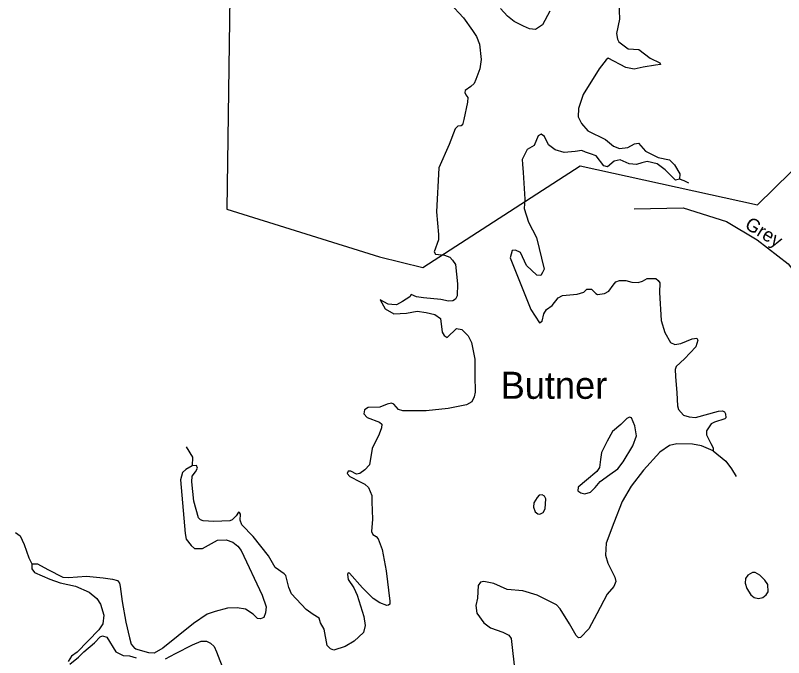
# Model space of a CAD drawing. Extents: x 2056842 to 2160602, y 826753 to 1016856.
# Drawn here: x 2065133 to 2070531, y 880850 to 885359 of the extents above; entities that cross this region are included whole.
import ezdxf

# ---------------------------------------------------------------- set-up
doc = ezdxf.new("R2010")
doc.units = 0
for name, color, linetype in [('Exist Boundary Land Use Reservation Military US Department of Defense', 7, 'Continuous'), ('Exist Hydrographic Lake Shore', 7, 'Continuous'), ('Exist Hydrographic Lake Shore Label', 7, 'Continuous'), ('Exist Hydrographic Misc Water Feature', 7, 'Continuous'), ('Exist Road Non-System Type 51', 7, 'Continuous'), ('Exist Road Non-System Type 51 Label', 7, 'Continuous')]:
    doc.layers.add(name, color=color, linetype=linetype)

msp = doc.modelspace()

# ---------------------------------------------------------------- linework, layer by layer
at = {"layer": 'Exist Boundary Land Use Reservation Military US Department of Defense'}
msp.add_lwpolyline([(2067058.3, 892019.1), (2067059.5, 891358.5), (2066982.6, 890921.4), (2067567.8, 890285), (2067430.4, 890017.5), (2067627.8, 889522.4), (2067456.3, 889295), (2067709.3, 888998.5), (2067120, 887398.5), (2066967.8, 887049.6), (2067058.5, 886712.6), (2066509.4, 886235.5), (2066262.8, 886013.6), (2066639, 885490.3), (2066618.5, 883998.2), (2067691.7, 883663.3), (2067994.8, 883588.2), (2069101.6, 884301.6), (2070346.7, 884029), (2071050.9, 884719.7)], dxfattribs=at)
at = {"layer": 'Exist Hydrographic Lake Shore'}
for points in [[(2069373.7, 885453.7), (2069376.3, 885332.1), (2069357.3, 885230.7), (2069362.3, 885192.7), (2069373.7, 885173.7), (2069438.7, 885124.1), (2069512.8, 885120.2), (2069592.7, 885058.3), (2069660.9, 885026.5), (2069664.9, 885014.4), (2069629.5, 885009.6), (2069544.3, 884994.4), (2069479.7, 884981.8), (2069421.5, 884991.9), (2069298.6, 885057.8), (2069284.7, 885047.6), (2069235.3, 884983), (2069122.6, 884804.4), (2069088.5, 884704.3), (2069087.2, 884647.3), (2069111.2, 884600.4), (2069155.6, 884548.5), (2069278.4, 884487.7), (2069334.1, 884440.8), (2069378.3, 884424.3), (2069435.3, 884430.6), (2069482.1, 884456), (2069511.2, 884461.1), (2069560.6, 884406.6), (2069649.2, 884361), (2069727.7, 884345.8), (2069763.2, 884309), (2069801.2, 884245.7), (2069799.9, 884208.9)], [(2068185.5, 885445.4), (2068280.4, 885341.5), (2068343.7, 885251.6), (2068371.6, 885211), (2068393.1, 885157.2), (2068404.5, 885049.5), (2068395.7, 884983.6), (2068367.8, 884908.9), (2068356.4, 884881), (2068332.4, 884860.7), (2068293.1, 884832.1), (2068291.8, 884818.1), (2068298.2, 884801.7), (2068310.8, 884781.4), (2068308.3, 884749.7), (2068284.2, 884628.1), (2068274.1, 884591.4), (2068265.2, 884583.8), (2068242.5, 884580), (2068222.2, 884561.2), (2068181.7, 884453.3), (2068107, 884289.1), (2068090.5, 883980.3), (2068105.1, 883819.6), (2068105.2, 883783.6), (2068075.4, 883697.6), (2068083.5, 883681.6), (2068147.6, 883675.7), (2068184.2, 883662), (2068203.2, 883640.4), (2068226, 883608.7), (2068238.7, 883473.2), (2068237.4, 883390.8), (2068226, 883365.9), (2068205.7, 883354.5), (2068176.6, 883353.2), (2068120.9, 883364.6), (2068000.6, 883374.7), (2067950, 883382.3), (2067914.5, 883398.8), (2067903.1, 883383.6), (2067852.2, 883349.7), (2067811.7, 883325.6), (2067778.8, 883328.1), (2067752.2, 883330.7), (2067695.2, 883361.1), (2067730.7, 883297.7), (2067791.5, 883263.5), (2067880.1, 883268.6), (2067954.8, 883281.2), (2068019.4, 883272.4), (2068078.9, 883258.4), (2068120.7, 883231.8), (2068130.4, 883135.8), (2068146.5, 883111.7), (2068166.6, 883097.8), (2068233.3, 883161.1), (2068268.8, 883153.5), (2068314.5, 883110), (2068338.4, 883062.3), (2068361.2, 882944.5), (2068361.1, 882830.2)], [(2068888.7, 885389.6), (2068835.5, 885292.1), (2068787.4, 885259.2), (2068745.1, 885264.2), (2068702.1, 885282), (2068638, 885316.2), (2068590.3, 885354.4), (2068540.2, 885408.3)], [(2069799.9, 884208.9), (2069770.8, 884202.6), (2069697.4, 884273.6), (2069641.6, 884316.6), (2069571.8, 884333.1), (2069533.8, 884324.2), (2069495.8, 884312.8), (2069446.4, 884316.6), (2069383.1, 884344.5), (2069340, 884334.4), (2069293.2, 884295.1), (2069266.6, 884302.7), (2069213.4, 884372.4), (2069174.6, 884386.3), (2069139.1, 884399), (2069112.5, 884409.1), (2069066.9, 884404), (2068988.4, 884395.2), (2068926.4, 884414.2), (2068877.9, 884450.9), (2068851.4, 884507.9), (2068826.1, 884524.4), (2068805.8, 884513), (2068776.7, 884445.9), (2068728.6, 884416.7), (2068694.1, 884346.7), (2068697, 884314.1), (2068700.8, 884255.8), (2068713.4, 884068.9), (2068708.4, 884003.1), (2068737.5, 883906.8), (2068793.2, 883800.4), (2068847.6, 883577.4), (2068835.7, 883553.1), (2068823.7, 883532.9), (2068795.7, 883534.9), (2068723.5, 883602.8), (2068681.8, 883695.2), (2068647.4, 883710.6), (2068623.3, 883708.7), (2068608.3, 883657.2), (2068753.4, 883294.2), (2068814.2, 883200.5), (2068833.2, 883211.9), (2068844.6, 883263.8), (2068864.9, 883293), (2068904.1, 883320.8), (2068945.9, 883375.3), (2068977.5, 883391.8), (2069080, 883400.6), (2069126.8, 883414.6), (2069147.1, 883437.4), (2069180, 883436.1), (2069210.4, 883407), (2069223.1, 883398.1), (2069271.2, 883407), (2069301.6, 883422.2), (2069331.9, 883465.3), (2069352.5, 883488.1), (2069376.5, 883498.2), (2069422.1, 883496.9), (2069465.1, 883485.5), (2069509.5, 883484.3), (2069538.6, 883493.1), (2069572.8, 883512.1), (2069633.5, 883512.1), (2069650, 883496.9), (2069660.1, 883480.5), (2069658.9, 883412.7), (2069670.3, 883216.9), (2069696.9, 883132.1), (2069736.1, 883061.1), (2069766.5, 883047.2), (2069809.5, 883056), (2069888, 883089), (2069919.7, 883092.8), (2069928.6, 883078.8), (2069913.4, 883032), (2069833.6, 882948.3), (2069776.6, 882893.9), (2069769, 882872.3), (2069771.6, 882824.2), (2069780.4, 882708.9), (2069785.5, 882616.4), (2069793.1, 882592.3), (2069826, 882551.8), (2069866.5, 882539.1), (2069912.1, 882535.3), (2070073.4, 882579.4), (2070102, 882582.2), (2070116, 882574.6), (2070122.3, 882560.7), (2070124.8, 882534.1), (2070117.2, 882525.2), (2070043.8, 882502.4), (2070021, 882491), (2069988.1, 882440.9), (2069988.1, 882413.1), (2070018.5, 882352.3), (2070036.2, 882323.1), (2070036.2, 882301.6)], [(2069864.5, 884179.8), (2069831.6, 884197.5), (2069799.9, 884208.9)], [(2068361.1, 882830.2), (2068363.8, 882714.4), (2068357.4, 882681.5), (2068339.7, 882645.3), (2068303, 882623.7), (2068173.8, 882599.6), (2068018.1, 882583.2), (2067856, 882581.9), (2067824.4, 882590.8), (2067792.7, 882630.1), (2067776.3, 882636.4), (2067745.9, 882630.1), (2067694, 882608.5), (2067611.7, 882604.7), (2067585.1, 882589.5), (2067581.3, 882561.6), (2067604.1, 882536.3), (2067691.4, 882503.4), (2067706.6, 882488.2), (2067705.4, 882464.1), (2067687.6, 882418.5), (2067639.5, 882317.1), (2067620.5, 882203.9), (2067588.9, 882168.4), (2067552.1, 882143.1), (2067530.6, 882138), (2067488.8, 882159.5), (2067469.8, 882158.3), (2067463.5, 882141.8), (2067482.5, 882121.5), (2067554.7, 882084.8), (2067588.9, 882067), (2067614.2, 882043), (2067637, 881988.5), (2067638.2, 881944.1), (2067642, 881822), (2067635.7, 881734.6), (2067643.3, 881714.3), (2067667.4, 881699.1), (2067681.3, 881683.9), (2067709.2, 881607.9), (2067737, 881459), (2067763.6, 881246.2), (2067763.6, 881225.9), (2067754.7, 881217.1), (2067742.1, 881214.5), (2067692.7, 881234.8), (2067647.1, 881263.9), (2067572.4, 881340), (2067480, 881442.6), (2067471.1, 881445.1), (2067466, 881432.4), (2067469.8, 881397), (2067511.6, 881338.7), (2067533.2, 881289.3), (2067581.3, 881138.5), (2067590.1, 881074.3), (2067578.7, 881026.1), (2067514.2, 880964.1), (2067450.9, 880927.3), (2067371.1, 880902), (2067347, 880910.9), (2067324.2, 880934.9), (2067301.4, 881050.2), (2067277.4, 881093.3), (2067267.3, 881126.2), (2067224.2, 881152.8), (2067176.1, 881188.3), (2067072.3, 881298.5), (2067054.5, 881342.9), (2067033, 881425.9), (2067020.4, 881437.3), (2066958.3, 881482.9), (2066910.2, 881565.2), (2066802.6, 881699.5), (2066722.8, 881782.6), (2066711.4, 881815.6), (2066714, 881856.1), (2066707.6, 881868.8), (2066701.3, 881870), (2066683.6, 881846), (2066657, 881818.1), (2066640.5, 881810.5), (2066527.8, 881805.4), (2066453.1, 881810.5), (2066434.1, 881816.8), (2066418.9, 881832), (2066387.3, 881947.3), (2066372.1, 882084.1), (2066375.9, 882123), (2066398.7, 882154.7), (2066411.3, 882180), (2066406.4, 882198.6), (2066374.3, 882196.5)], [(2066333.3, 882329.7), (2066376.2, 882256.5), (2066374.3, 882196.5)], [(2070036.2, 882301.6), (2069952.6, 882335.8), (2069889.4, 882348.5), (2069779.3, 882349.7), (2069729.9, 882339.6), (2069661.5, 882292.7), (2069546.3, 882164.8), (2069458.9, 882054.5), (2069396.3, 881946.8), (2069336.8, 881796.1), (2069284.8, 881652.9), (2069279.8, 881569.3), (2069296.2, 881512.3), (2069344.3, 881414.7), (2069351.9, 881383.1), (2069336.8, 881348.9), (2069291.2, 881294.4), (2069217.7, 881157.5), (2069160.8, 881052.4), (2069102.5, 880990.3), (2069088.6, 880989), (2069072.1, 881004.3), (2069025.3, 881087.9), (2068960.7, 881193), (2068934.1, 881220.9), (2068799.9, 881287), (2068697.3, 881318.7), (2068588.4, 881328.8), (2068493.5, 881370.6), (2068423.8, 881384.6), (2068399.8, 881379.5), (2068384.6, 881356.7), (2068380.8, 881268), (2068368.1, 881214.8), (2068374.5, 881161.6), (2068423.8, 881094.5), (2068472, 881059.6), (2068558.1, 881027.9), (2068599.8, 881006.4), (2068616.3, 880984.9), (2068644.2, 880734)], [(2070036.2, 882301.6), (2070124.8, 882229.4), (2070165.3, 882174.9), (2070197, 882121.7)], [(2066374.3, 882196.5), (2066330.3, 882169.9), (2066306.3, 882148.4), (2066293.6, 882097.7), (2066325.3, 881720.4), (2066333.2, 881680.5), (2066367.3, 881636.6), (2066391.3, 881616.5), (2066446.8, 881616.7), (2066553.2, 881673.7), (2066613.9, 881677.5), (2066659.5, 881661), (2066695.3, 881633.2), (2066719.5, 881601.1), (2066865.9, 881289.2), (2066893.7, 881205.5), (2066891.2, 881163.7), (2066877.3, 881130.8), (2066854.5, 881121.9), (2066833, 881124.5), (2066802.6, 881154.9), (2066750.7, 881189.2), (2066689.9, 881198.1), (2066624.1, 881196.8), (2066536.2, 881172.8), (2066479.7, 881153.7), (2066383.5, 881090.4), (2066168.9, 880915.3), (2066106.7, 880882), (2066070.7, 880884), (2065978.6, 880907.9), (2065970.8, 880915.8)], [(2065132.6, 881729.2), (2065167.4, 881704.3), (2065195.3, 881644.3), (2065227.6, 881550.3), (2065247.7, 881508.4)], [(2065247.7, 881508.4), (2065287.7, 881508.4), (2065359.7, 881468.5), (2065466, 881414.9), (2065506.6, 881411.1), (2065633.2, 881422.5), (2065748.4, 881409.8), (2065815, 881400.6), (2065849.2, 881391.1), (2065865, 881372.1), (2065868.8, 881348.6), (2065884, 881244.7), (2065908, 881099), (2065934.5, 880987.8), (2065946, 880944.4), (2065970.8, 880915.8)], [(2065247.7, 881508.4), (2065247.8, 881472.4), (2065267.7, 881448.4), (2065374.9, 881401), (2065448.3, 881375.6), (2065555.9, 881351.1), (2065652.1, 881309.3), (2065704, 881265.2), (2065730.2, 881225.2), (2065754.3, 881147.3), (2065746.3, 881087.3), (2065718.4, 881045.3), (2065566.8, 880889), (2065526.8, 880859), (2065502.8, 880822.9)], [(2065515, 880803), (2065576.2, 880852.9), (2065612.9, 880889.6), (2065687.6, 880954.2), (2065728.1, 880994.8), (2065745.9, 881003.7), (2065775, 880992.2), (2065838.3, 880889.6), (2065888.9, 880864.3), (2065934.9, 880861.8)], [(2066186.5, 880841.5), (2066258.7, 880879.5), (2066377.7, 880940.3), (2066437.2, 880964.4), (2066475.2, 880964.4), (2066503, 880951.7), (2066528.4, 880927.6), (2066546.8, 880890.9), (2066597, 880756.9)], [(2065934.9, 880861.8), (2065981.4, 880847.8)]]:
    msp.add_lwpolyline(points, dxfattribs=at)
at = {"layer": 'Exist Hydrographic Misc Water Feature'}
for points in [[(2069327.4, 882436.8), (2069289.7, 882369.2), (2069252, 882290.6), (2069244.1, 882241.8), (2069236.3, 882185.2), (2069217.4, 882155.4), (2069146.7, 882095.6), (2069087, 882046.9), (2069085.4, 882021.7), (2069105.8, 882006), (2069134.1, 881999.7), (2069173.4, 882012.3), (2069206.4, 882043.7), (2069241, 882086.2), (2069310.1, 882134.9), (2069365.1, 882174.2), (2069402.8, 882224.5), (2069472, 882336.2), (2069497.1, 882407), (2069484.6, 882476.1), (2069462.6, 882532.8), (2069448.4, 882537.5), (2069429.6, 882528), (2069387.1, 882485.6), (2069327.4, 882436.8)], [(2068772.6, 881906.9), (2068785.2, 881873.9), (2068802.5, 881858.2), (2068816.6, 881856.6), (2068840.2, 881869.2), (2068854.4, 881894.3), (2068859.1, 881963.5), (2068851.2, 881982.4), (2068833.9, 881991.8), (2068813.5, 881990.2), (2068797.8, 881974.5), (2068775.8, 881936.8), (2068772.6, 881906.9)], [(2070271.8, 881336), (2070300.4, 881290.5), (2070324.2, 881271.7), (2070354.8, 881264.8), (2070385.4, 881271.7), (2070408.1, 881290.5), (2070420.9, 881311.3), (2070419.9, 881363.6), (2070398.2, 881394.3), (2070362.7, 881428.9), (2070330.1, 881447.6), (2070312.3, 881446.7), (2070278.7, 881428.9), (2070262.9, 881405.1), (2070260, 881372.5), (2070271.8, 881336)]]:
    msp.add_lwpolyline(points, dxfattribs=at)
at = {"layer": 'Exist Road Non-System Type 51'}
msp.add_lwpolyline([(2069479.9, 884000.2), (2069824.6, 884008.2), (2070129.3, 883911.9), (2070345.7, 883783.6), (2070562.2, 883615.1), (2070698.5, 883438.6), (2070714.5, 883350.4), (2070794.7, 883149.8), (2070898.9, 882997.4), (2071027.2, 882877), (2071387.9, 882700.5), (2072191.9, 882318.6)], dxfattribs=at)

# ---------------------------------------------------------------- texts
at = {"layer": 'Exist Hydrographic Lake Shore Label'}
msp.add_text('Butner', height=190, dxfattribs=at).set_placement((2068542.6, 882666.7))
at = {"layer": 'Exist Road Non-System Type 51 Label'}
msp.add_text('Grey', height=95, rotation=328.3473, dxfattribs=at).set_placement((2070250.7, 883869.2))

doc.saveas('drawing.dxf')
